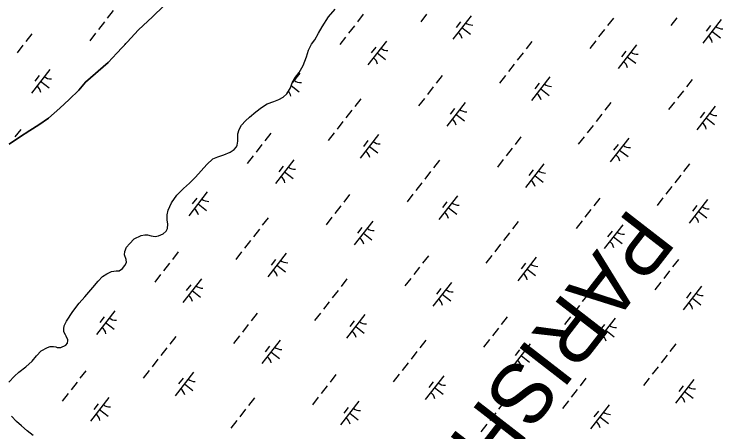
# Model space of a CAD drawing. Extents: x 3888273 to 3909528, y 158682 to 181032.
# Drawn here: x 3904884 to 3906064, y 170681 to 171377 of the extents above; entities that cross this region are included whole.
import ezdxf

# ---------------------------------------------------------------- set-up
doc = ezdxf.new("R2010")
doc.units = 0
for name, color, linetype in [('V-TOPO-GNAM-IDEN', 7, 'Continuous'), ('V-TOPO-SHOR', 7, 'Continuous'), ('V-WETL-SWMP', 7, 'Continuous')]:
    doc.layers.add(name, color=color, linetype=linetype)

msp = doc.modelspace()

# ---------------------------------------------------------------- linework, layer by layer
at = {"layer": 'V-TOPO-SHOR'}
for points in [[(3904875.2, 171160.3), (3904892.1, 171172), (3904909.5, 171183.3), (3904924.5, 171192.6), (3904940.7, 171203.9), (3904959.6, 171220.8), (3904975.3, 171235.2), (3904991, 171250.5), (3905002.4, 171263.7), (3905040.2, 171296.7), (3905054.7, 171312), (3905071.6, 171330.8), (3905090.9, 171350.9), (3905113.7, 171372.6), (3905132.6, 171391.4)], [(3905001.4, 170906.2), (3905014.3, 170921.4), (3905023.7, 170932.2), (3905030.7, 170939.8), (3905037.8, 170944.6), (3905045.7, 170948.2), (3905053.2, 170949.1), (3905058.3, 170949.5), (3905063.8, 170953.2), (3905068.1, 170958), (3905070.9, 170963.1), (3905070, 170968.3), (3905067.2, 170976.2), (3905067.9, 170981.7), (3905070.6, 170988.9), (3905075.7, 170994.5), (3905083.5, 171002.5), (3905094.9, 171008.1), (3905101.3, 171009.4), (3905105.6, 171009.4), (3905112, 171007.9), (3905118.3, 171006.4), (3905124.2, 171007.6), (3905131.7, 171011.3), (3905136.8, 171015.3), (3905138.8, 171020.1), (3905139.5, 171027.2), (3905138.6, 171034.3), (3905138.5, 171042.6), (3905140, 171050.6), (3905145.8, 171062.5), (3905154.4, 171075.3), (3905165.4, 171086.8), (3905175.6, 171095.7), (3905185.8, 171105.3), (3905195.2, 171116.1), (3905204.5, 171126.8), (3905214.7, 171136.1), (3905223, 171139.3), (3905232.9, 171142.6), (3905243.1, 171147), (3905249.8, 171151.9), (3905253.7, 171155.9), (3905254.9, 171158.7), (3905256.4, 171165.8), (3905255.9, 171177.7), (3905258.6, 171185.2), (3905262, 171192.4), (3905268.7, 171199.6), (3905275.4, 171205.6), (3905286, 171214.4), (3905295.8, 171221.6), (3905304.8, 171227.7), (3905315.9, 171231.7), (3905324.5, 171235), (3905331.6, 171239), (3905337.9, 171244.6), (3905343.7, 171254.6), (3905346.8, 171262.5), (3905352.3, 171272.1), (3905358.1, 171280.1), (3905365.1, 171291.6), (3905370.5, 171305.9), (3905373.6, 171317.1), (3905378.6, 171327), (3905384.5, 171334.6), (3905390.3, 171345.3), (3905396.5, 171356.1), (3905407.4, 171372.8), (3905418.4, 171385.6)], [(3904874.6, 170763.5), (3904884, 170773.9), (3904891.1, 170780.3), (3904902.9, 170789.2), (3904913.4, 170798.8), (3904920.9, 170807.6), (3904928.3, 170816), (3904939.3, 170821.6), (3904943.3, 170823.2), (3904948.8, 170823.3), (3904952.8, 170822.5), (3904955.2, 170821.8), (3904961.5, 170821.8), (3904969.4, 170825.5), (3904972.1, 170828.7), (3904972.9, 170833.4), (3904972.8, 170834.2), (3904970.4, 170840.5), (3904969.2, 170842.5), (3904966, 170847.6), (3904966.3, 170852.4), (3904966.7, 170857.5), (3904970.5, 170865.5), (3904981.5, 170881.8), (3904991.6, 170895.4), (3905001.4, 170906.2)], [(3904915.1, 170674.9), (3904905.2, 170682.7), (3904895.6, 170690.9), (3904887.6, 170698.3), (3904879.2, 170707)]]:
    msp.add_lwpolyline(points, dxfattribs=at)
at = {"layer": 'V-WETL-SWMP'}
for p, q in [((3905132.6, 171391.4), (3905113.7, 171372.6)), ((3905048.6, 171383.2), (3905038.7, 171370.6)), ((3905407.4, 171372.8), (3905418.4, 171385.6)), ((3905465.2, 171377), (3905455.4, 171364.3)), ((3905570.7, 171377.2), (3905560.9, 171364.6)), ((3905113.7, 171372.6), (3905090.9, 171350.9)), ((3905396.5, 171356.1), (3905407.4, 171372.8)), ((3905644.8, 171374.7), (3905614.1, 171335.3)), ((3905881.9, 171370.7), (3905872.1, 171358.1)), ((3905987.4, 171371), (3905977.5, 171358.4)), ((3906061.5, 171368.5), (3906030.8, 171329.1)), ((3905033.8, 171364.3), (3905024, 171351.6)), ((3905390.3, 171345.3), (3905396.5, 171356.1)), ((3905450.5, 171358), (3905440.7, 171345.4)), ((3905627.1, 171364.5), (3905619.7, 171355)), ((3905629.5, 171355), (3905643.7, 171344)), ((3906043.7, 171358.3), (3906036.4, 171348.8)), ((3904912.8, 171344.3), (3904903, 171331.7)), ((3905019.1, 171345.3), (3905009.3, 171332.7)), ((3905090.9, 171350.9), (3905071.6, 171330.8)), ((3905384.5, 171334.6), (3905390.3, 171345.3)), ((3905867.2, 171351.8), (3905857.3, 171339.2)), ((3906046.1, 171348.8), (3906060.4, 171337.7)), ((3905071.6, 171330.8), (3905054.7, 171312)), ((3905378.6, 171327), (3905384.5, 171334.6)), ((3905435.8, 171339.1), (3905425.9, 171326.5)), ((3905503.6, 171332.3), (3905472.9, 171292.8)), ((3905746.2, 171331.9), (3905736.4, 171319.3)), ((3905852.4, 171332.9), (3905842.6, 171320.2)), ((3904898.1, 171325.4), (3904888.3, 171312.8)), ((3905069.2, 171328.3), (3905068, 171326.7)), ((3905373.6, 171317.1), (3905378.6, 171327)), ((3905485.8, 171322), (3905478.5, 171312.6)), ((3905920.3, 171326.1), (3905889.6, 171286.6)), ((3905054.7, 171312), (3905040.2, 171296.7)), ((3905365.1, 171291.6), (3905370.5, 171305.9)), ((3905370.5, 171305.9), (3905373.6, 171317.1)), ((3905488.2, 171312.6), (3905502.4, 171301.5)), ((3905731.4, 171313), (3905721.6, 171300.3)), ((3905902.5, 171315.8), (3905895.1, 171306.3)), ((3905904.9, 171306.3), (3905919.1, 171295.3)), ((3905040.2, 171296.7), (3905002.4, 171263.7)), ((3905716.7, 171294), (3905706.9, 171281.4)), ((3904942.8, 171285), (3904912.1, 171245.6)), ((3905358.1, 171280.1), (3905365.1, 171291.6)), ((3904925, 171274.8), (3904917.7, 171265.3)), ((3905346.8, 171262.5), (3905352.3, 171272.1)), ((3905359.4, 171278.8), (3905346.9, 171262.7)), ((3905352.3, 171272.1), (3905358.1, 171280.1)), ((3905596.5, 171274.8), (3905586.7, 171262.2)), ((3905702, 171275.1), (3905692.1, 171262.4)), ((3905776.1, 171272.6), (3905745.4, 171233.1)), ((3904927.4, 171265.3), (3904941.6, 171254.3)), ((3905002.4, 171263.7), (3904991, 171250.5)), ((3905343.7, 171254.6), (3905346.8, 171262.5)), ((3905345.2, 171258.3), (3905358.3, 171248)), ((3905758.4, 171262.3), (3905751, 171252.9)), ((3906013.2, 171268.6), (3906003.4, 171256)), ((3904991, 171250.5), (3904975.3, 171235.2)), ((3905337.9, 171244.6), (3905343.7, 171254.6)), ((3905581.8, 171255.9), (3905571.9, 171243.3)), ((3905760.8, 171252.9), (3905775, 171241.8)), ((3905998.4, 171249.7), (3905988.6, 171237)), ((3904975.3, 171235.2), (3904959.6, 171220.8)), ((3905315.9, 171231.7), (3905324.5, 171235)), ((3905324.5, 171235), (3905331.6, 171239)), ((3905331.6, 171239), (3905337.9, 171244.6)), ((3905460.8, 171236), (3905451, 171223.3)), ((3905567, 171236.9), (3905557.2, 171224.3)), ((3905295.8, 171221.6), (3905304.8, 171227.7)), ((3905304.8, 171227.7), (3905315.9, 171231.7)), ((3905634.9, 171230.1), (3905604.2, 171190.7)), ((3905877.5, 171229.8), (3905867.6, 171217.1)), ((3905983.7, 171230.7), (3905973.9, 171218.1)), ((3906051.5, 171223.9), (3906020.8, 171184.5)), ((3904959.6, 171220.8), (3904940.7, 171203.9)), ((3905275.4, 171205.6), (3905286, 171214.4)), ((3905286, 171214.4), (3905295.8, 171221.6)), ((3905446.1, 171217), (3905436.2, 171204.4)), ((3905617.1, 171219.9), (3905609.7, 171210.4)), ((3906033.8, 171213.7), (3906026.4, 171204.2)), ((3904940.7, 171203.9), (3904924.5, 171192.6)), ((3905262, 171192.4), (3905268.7, 171199.6)), ((3905268.7, 171199.6), (3905275.4, 171205.6)), ((3905619.5, 171210.4), (3905633.7, 171199.4)), ((3905862.7, 171210.8), (3905852.9, 171198.2)), ((3906036.2, 171204.2), (3906050.4, 171193.1)), ((3904924.5, 171192.6), (3904909.5, 171183.3)), ((3905258.6, 171185.2), (3905262, 171192.4)), ((3905431.3, 171198.1), (3905421.5, 171185.5)), ((3905848, 171191.9), (3905838.2, 171179.2)), ((3904894.5, 171185.1), (3904884.6, 171172.5)), ((3904909.5, 171183.3), (3904892.1, 171172)), ((3905255.9, 171177.7), (3905258.6, 171185.2)), ((3905256.4, 171165.8), (3905255.9, 171177.7)), ((3905311.1, 171178.9), (3905301.3, 171166.3)), ((3905416.6, 171179.2), (3905406.8, 171166.5)), ((3905490.7, 171176.7), (3905460, 171137.2)), ((3904892.1, 171172), (3904875.2, 171160.3)), ((3905254.9, 171158.7), (3905256.4, 171165.8)), ((3905473, 171166.4), (3905465.6, 171156.9)), ((3905727.8, 171172.7), (3905718, 171160.1)), ((3905833.3, 171172.9), (3905823.4, 171160.3)), ((3905907.4, 171170.5), (3905876.7, 171131)), ((3905249.8, 171151.9), (3905253.7, 171155.9)), ((3905253.7, 171155.9), (3905254.9, 171158.7)), ((3905296.4, 171160), (3905286.6, 171147.3)), ((3905475.4, 171156.9), (3905489.6, 171145.9)), ((3905713.1, 171153.7), (3905703.2, 171141.1)), ((3905889.6, 171160.2), (3905882.3, 171150.7)), ((3905223, 171139.3), (3905232.9, 171142.6)), ((3905232.9, 171142.6), (3905243.1, 171147)), ((3905243.1, 171147), (3905249.8, 171151.9)), ((3905281.6, 171141), (3905271.8, 171128.4)), ((3905892, 171150.7), (3905906.2, 171139.7)), ((3905204.5, 171126.8), (3905214.7, 171136.1)), ((3905214.7, 171136.1), (3905223, 171139.3)), ((3905349.5, 171134.2), (3905318.8, 171094.8)), ((3905592.1, 171133.8), (3905582.3, 171121.2)), ((3905698.3, 171134.8), (3905688.5, 171122.2)), ((3905195.2, 171116.1), (3905204.5, 171126.8)), ((3905331.7, 171124), (3905324.4, 171114.5)), ((3905766.2, 171128), (3905735.4, 171088.5)), ((3905748.4, 171117.7), (3905741, 171108.3)), ((3906008.7, 171127.6), (3905998.9, 171115)), ((3905175.6, 171095.7), (3905185.8, 171105.3)), ((3905185.8, 171105.3), (3905195.2, 171116.1)), ((3905334.1, 171114.5), (3905348.3, 171103.4)), ((3905577.3, 171114.9), (3905567.5, 171102.3)), ((3905750.8, 171108.3), (3905765, 171097.2)), ((3905994, 171108.7), (3905984.2, 171096)), ((3905165.4, 171086.8), (3905175.6, 171095.7)), ((3905562.6, 171095.9), (3905552.8, 171083.3)), ((3905154.4, 171075.3), (3905165.4, 171086.8)), ((3905979.3, 171089.7), (3905969.4, 171077.1)), ((3905145.8, 171062.5), (3905154.4, 171075.3)), ((3905205.3, 171080.8), (3905174.6, 171041.3)), ((3905187.6, 171070.5), (3905180.2, 171061)), ((3905442.4, 171076.8), (3905432.6, 171064.1)), ((3905547.9, 171077), (3905538, 171064.4)), ((3905622, 171074.5), (3905591.3, 171035.1)), ((3905859.1, 171070.5), (3905849.2, 171057.9)), ((3905964.5, 171070.8), (3905954.7, 171058.2)), ((3905140, 171050.6), (3905145.8, 171062.5)), ((3905190, 171061), (3905204.2, 171050)), ((3905427.7, 171057.8), (3905417.8, 171045.2)), ((3905604.3, 171064.3), (3905596.9, 171054.8)), ((3906038.7, 171068.3), (3906008, 171028.8)), ((3906020.9, 171058), (3906013.5, 171048.6)), ((3905138.5, 171042.6), (3905140, 171050.6)), ((3905606.7, 171054.8), (3905620.9, 171043.7)), ((3905844.3, 171051.6), (3905834.5, 171039)), ((3906023.3, 171048.6), (3906037.5, 171037.5)), ((3905138.6, 171034.3), (3905138.5, 171042.6)), ((3905139.5, 171027.2), (3905138.6, 171034.3)), ((3905306.7, 171037.9), (3905296.9, 171025.3)), ((3905412.9, 171038.9), (3905403.1, 171026.3)), ((3905138.8, 171020.1), (3905139.5, 171027.2)), ((3905480.8, 171032.1), (3905450.1, 170992.6)), ((3905723.4, 171031.7), (3905713.5, 171019.1)), ((3905829.6, 171032.7), (3905819.8, 171020)), ((3905897.4, 171025.9), (3905866.7, 170986.4)), ((3905124.2, 171007.6), (3905131.7, 171011.3)), ((3905131.7, 171011.3), (3905136.8, 171015.3)), ((3905136.8, 171015.3), (3905138.8, 171020.1)), ((3905292, 171019), (3905282.1, 171006.3)), ((3905463, 171021.8), (3905455.6, 171012.4)), ((3905465.4, 171012.4), (3905479.6, 171001.3)), ((3905708.6, 171012.7), (3905698.8, 171000.1)), ((3905879.7, 171015.6), (3905872.3, 171006.1)), ((3905075.7, 170994.5), (3905083.5, 171002.5)), ((3905083.5, 171002.5), (3905094.9, 171008.1)), ((3905094.9, 171008.1), (3905101.3, 171009.4)), ((3905101.3, 171009.4), (3905105.6, 171009.4)), ((3905105.6, 171009.4), (3905112, 171007.9)), ((3905112, 171007.9), (3905118.3, 171006.4)), ((3905118.3, 171006.4), (3905124.2, 171007.6)), ((3905277.2, 171000), (3905267.4, 170987.4)), ((3905882.1, 171006.1), (3905896.3, 170995.1)), ((3905067.9, 170981.7), (3905070.6, 170988.9)), ((3905070.6, 170988.9), (3905075.7, 170994.5)), ((3905693.9, 170993.8), (3905684.1, 170981.2)), ((3905067.2, 170976.2), (3905067.9, 170981.7)), ((3905070, 170968.3), (3905067.2, 170976.2)), ((3905157, 170980.8), (3905147.2, 170968.2)), ((3905262.5, 170981.1), (3905252.7, 170968.5)), ((3905336.6, 170978.6), (3905305.9, 170939.2)), ((3905068.1, 170958), (3905070.9, 170963.1)), ((3905070.9, 170963.1), (3905070, 170968.3)), ((3905318.9, 170968.4), (3905311.5, 170958.9)), ((3905573.7, 170974.6), (3905563.9, 170962)), ((3905679.1, 170974.9), (3905669.3, 170962.2)), ((3905753.3, 170972.4), (3905722.6, 170932.9)), ((3905990.3, 170968.4), (3905980.5, 170955.8)), ((3905058.3, 170949.5), (3905063.8, 170953.2)), ((3905063.8, 170953.2), (3905068.1, 170958)), ((3905142.3, 170961.9), (3905132.5, 170949.3)), ((3905321.3, 170958.9), (3905335.5, 170947.8)), ((3905558.9, 170955.7), (3905549.1, 170943)), ((3905735.5, 170962.1), (3905728.2, 170952.7)), ((3905737.9, 170952.7), (3905752.1, 170941.6)), ((3905023.7, 170932.2), (3905030.7, 170939.8)), ((3905030.7, 170939.8), (3905037.8, 170944.6)), ((3905037.8, 170944.6), (3905045.7, 170948.2)), ((3905045.7, 170948.2), (3905053.2, 170949.1)), ((3905053.2, 170949.1), (3905058.3, 170949.5)), ((3905127.5, 170943), (3905117.7, 170930.3)), ((3905975.6, 170949.5), (3905965.8, 170936.8)), ((3905014.3, 170921.4), (3905023.7, 170932.2)), ((3905195.4, 170936.2), (3905164.7, 170896.7)), ((3905438, 170935.8), (3905428.1, 170923.1)), ((3905544.2, 170936.7), (3905534.4, 170924.1)), ((3905612, 170929.9), (3905581.3, 170890.5)), ((3905854.6, 170929.5), (3905844.8, 170916.9)), ((3905960.9, 170930.5), (3905951, 170917.9)), ((3905001.4, 170906.2), (3905014.3, 170921.4)), ((3905177.6, 170925.9), (3905170.3, 170916.4)), ((3905180, 170916.4), (3905194.2, 170905.4)), ((3905423.2, 170916.8), (3905413.4, 170904.2)), ((3905594.3, 170919.7), (3905586.9, 170910.2)), ((3906028.7, 170923.7), (3905998, 170884.3)), ((3904991.6, 170895.4), (3905001.4, 170906.2)), ((3905596.7, 170910.2), (3905610.9, 170899.2)), ((3905839.9, 170910.6), (3905830.1, 170898)), ((3906011, 170913.5), (3906003.6, 170904)), ((3904981.5, 170881.8), (3904991.6, 170895.4)), ((3905408.5, 170897.9), (3905398.7, 170885.3)), ((3906013.4, 170904), (3906027.6, 170892.9)), ((3904970.5, 170865.5), (3904981.5, 170881.8)), ((3905051.2, 170882.7), (3905020.5, 170843.2)), ((3905825.2, 170891.7), (3905815.3, 170879)), ((3905033.5, 170872.4), (3905026.1, 170863)), ((3905288.3, 170878.7), (3905278.5, 170866.1)), ((3905393.8, 170878.9), (3905383.9, 170866.3)), ((3905467.9, 170876.5), (3905437.2, 170837)), ((3905705, 170872.5), (3905695.1, 170859.8)), ((3905810.4, 170872.7), (3905800.6, 170860.1)), ((3905884.6, 170870.2), (3905853.9, 170830.8)), ((3904966.3, 170852.4), (3904966.7, 170857.5)), ((3904966.7, 170857.5), (3904970.5, 170865.5)), ((3905035.9, 170863), (3905050.1, 170851.9)), ((3905273.6, 170859.8), (3905263.7, 170847.1)), ((3905450.1, 170866.2), (3905442.8, 170856.7)), ((3905866.8, 170860), (3905859.4, 170850.5)), ((3904966, 170847.6), (3904966.3, 170852.4)), ((3904969.2, 170842.5), (3904966, 170847.6)), ((3905452.5, 170856.7), (3905466.8, 170845.7)), ((3905690.2, 170853.5), (3905680.4, 170840.9)), ((3905869.2, 170850.5), (3905883.4, 170839.5)), ((3904970.4, 170840.5), (3904969.2, 170842.5)), ((3904972.8, 170834.2), (3904970.4, 170840.5)), ((3904972.1, 170828.7), (3904972.9, 170833.4)), ((3904972.9, 170833.4), (3904972.8, 170834.2)), ((3905152.6, 170839.8), (3905142.8, 170827.2)), ((3905258.8, 170840.8), (3905249, 170828.2)), ((3905326.7, 170834), (3905296, 170794.6)), ((3905569.3, 170833.6), (3905559.4, 170821)), ((3905675.5, 170834.6), (3905665.7, 170822)), ((3904928.3, 170816), (3904939.3, 170821.6)), ((3904939.3, 170821.6), (3904943.3, 170823.2)), ((3904943.3, 170823.2), (3904948.8, 170823.3)), ((3904948.8, 170823.3), (3904952.8, 170822.5)), ((3904952.8, 170822.5), (3904955.2, 170821.8)), ((3904955.2, 170821.8), (3904961.5, 170821.8)), ((3904961.5, 170821.8), (3904969.4, 170825.5)), ((3904969.4, 170825.5), (3904972.1, 170828.7)), ((3905308.9, 170823.8), (3905301.5, 170814.3)), ((3905743.3, 170827.8), (3905712.6, 170788.3)), ((3905985.9, 170827.4), (3905976.1, 170814.8)), ((3904920.9, 170807.6), (3904928.3, 170816)), ((3905137.8, 170820.9), (3905128, 170808.3)), ((3905311.3, 170814.3), (3905325.5, 170803.2)), ((3905554.5, 170814.7), (3905544.7, 170802.1)), ((3905725.6, 170817.5), (3905718.2, 170808.1)), ((3904902.9, 170789.2), (3904913.4, 170798.8)), ((3904913.4, 170798.8), (3904920.9, 170807.6)), ((3905123.1, 170802), (3905113.3, 170789.3)), ((3905728, 170808.1), (3905742.2, 170797)), ((3905971.2, 170808.5), (3905961.4, 170795.8)), ((3904891.1, 170780.3), (3904902.9, 170789.2)), ((3905539.8, 170795.7), (3905530, 170783.1)), ((3905956.4, 170789.5), (3905946.6, 170776.9)), ((3904884, 170773.9), (3904891.1, 170780.3)), ((3905002.9, 170782.8), (3904993.1, 170770.2)), ((3905108.4, 170783), (3905098.5, 170770.4)), ((3905182.5, 170780.6), (3905151.8, 170741.1)), ((3905419.6, 170776.6), (3905409.8, 170763.9)), ((3905525, 170776.8), (3905515.2, 170764.2)), ((3905599.2, 170774.3), (3905568.5, 170734.9)), ((3904874.6, 170763.5), (3904884, 170773.9)), ((3904988.2, 170763.8), (3904978.3, 170751.2)), ((3905164.8, 170770.3), (3905157.4, 170760.8)), ((3905581.4, 170764.1), (3905574.1, 170754.6)), ((3905836.2, 170770.3), (3905826.4, 170757.7)), ((3905941.7, 170770.6), (3905931.9, 170757.9)), ((3906015.8, 170768.1), (3905985.1, 170728.6)), ((3905167.2, 170760.8), (3905181.4, 170749.8)), ((3905404.8, 170757.6), (3905395, 170745)), ((3905583.8, 170754.6), (3905598, 170743.5)), ((3905821.5, 170751.4), (3905811.7, 170738.8)), ((3905998.1, 170757.8), (3905990.7, 170748.4)), ((3904973.4, 170744.9), (3904963.6, 170732.3)), ((3906000.5, 170748.4), (3906014.7, 170737.3)), ((3905041.3, 170738.1), (3905010.6, 170698.6)), ((3905023.5, 170727.8), (3905016.1, 170718.4)), ((3905283.9, 170737.7), (3905274, 170725.1)), ((3905390.1, 170738.7), (3905380.3, 170726)), ((3905457.9, 170731.9), (3905427.2, 170692.4)), ((3905700.5, 170731.5), (3905690.7, 170718.9)), ((3905806.8, 170732.4), (3905796.9, 170719.8)), ((3905025.9, 170718.4), (3905040.1, 170707.3)), ((3905269.1, 170718.8), (3905259.3, 170706.1)), ((3905440.2, 170721.6), (3905432.8, 170712.1)), ((3905874.6, 170725.7), (3905843.9, 170686.2)), ((3905856.9, 170715.4), (3905849.5, 170705.9)), ((3904887.6, 170698.3), (3904879.2, 170707)), ((3905442.6, 170712.1), (3905456.8, 170701.1)), ((3905685.8, 170712.5), (3905676, 170699.9)), ((3905859.3, 170705.9), (3905873.5, 170694.9)), ((3904895.6, 170690.9), (3904887.6, 170698.3)), ((3905254.4, 170699.8), (3905244.6, 170687.2)), ((3905671.1, 170693.6), (3905661.2, 170681)), ((3904905.2, 170682.7), (3904895.6, 170690.9)), ((3904915.1, 170674.9), (3904905.2, 170682.7))]:
    msp.add_line(p, q, dxfattribs=at)
for centre, start, end in [((3905646.6, 171376.7), 231.343, 272.8866), ((3906063.3, 171370.4), 231.343, 272.8866), ((3905612.7, 171333.1), 11.343, 52.8866), ((3906029.4, 171326.8), 11.343, 52.8866), ((3905505.4, 171334.2), 231.343, 272.8866), ((3905922.1, 171328), 231.343, 272.8866), ((3905471.5, 171290.6), 11.343, 52.8866), ((3905888.1, 171284.4), 11.343, 52.8866), ((3904944.6, 171287), 231.343, 272.8866), ((3905361.2, 171280.7), 231.343, 272.8866), ((3905777.9, 171274.5), 231.343, 272.8866), ((3904910.7, 171243.4), 11.343, 52.8866), ((3905327.3, 171237.1), 11.343, 41.9789), ((3905744, 171230.9), 11.343, 52.8866), ((3905636.7, 171232.1), 231.343, 272.8866), ((3906053.3, 171225.8), 231.343, 272.8866), ((3905602.7, 171188.5), 11.343, 52.8866), ((3906019.4, 171182.2), 11.343, 52.8866), ((3905492.5, 171178.6), 231.343, 272.8866), ((3905909.2, 171172.4), 231.343, 272.8866), ((3905458.6, 171135), 11.343, 52.8866), ((3905875.3, 171128.8), 11.343, 52.8866), ((3905351.3, 171136.2), 231.343, 272.8866), ((3905317.4, 171092.6), 11.343, 52.8866), ((3905768, 171129.9), 231.343, 272.8866), ((3905734, 171086.3), 11.343, 52.8866), ((3905207.1, 171082.7), 231.343, 272.8866), ((3905623.8, 171076.5), 231.343, 272.8866), ((3905173.2, 171039.1), 11.343, 52.8866), ((3905589.9, 171032.9), 11.343, 52.8866), ((3906040.5, 171070.2), 231.343, 272.8866), ((3906006.5, 171026.6), 11.343, 52.8866), ((3905482.6, 171034), 231.343, 272.8866), ((3905899.2, 171027.8), 231.343, 272.8866), ((3905448.6, 170990.4), 11.343, 52.8866), ((3905865.3, 170984.2), 11.343, 52.8866), ((3905338.4, 170980.5), 231.343, 272.8866), ((3905755.1, 170974.3), 231.343, 272.8866), ((3905304.5, 170936.9), 11.343, 52.8866), ((3905721.2, 170930.7), 11.343, 52.8866), ((3905197.2, 170938.1), 231.343, 272.8866), ((3905613.8, 170931.9), 231.343, 272.8866), ((3905163.3, 170894.5), 11.343, 52.8866), ((3906030.5, 170925.6), 231.343, 272.8866), ((3905579.9, 170888.3), 11.343, 52.8866), ((3905996.6, 170882), 11.343, 52.8866), ((3905053, 170884.6), 231.343, 272.8866), ((3905469.7, 170878.4), 231.343, 272.8866), ((3905886.4, 170872.2), 231.343, 272.8866), ((3905019.1, 170841), 11.343, 52.8866), ((3905435.8, 170834.8), 11.343, 52.8866), ((3905852.4, 170828.6), 11.343, 52.8866), ((3905328.5, 170835.9), 231.343, 272.8866), ((3905745.1, 170829.7), 231.343, 272.8866), ((3905294.5, 170792.3), 11.343, 52.8866), ((3905711.2, 170786.1), 11.343, 52.8866), ((3905184.3, 170782.5), 231.343, 272.8866), ((3905601, 170776.2), 231.343, 272.8866), ((3905150.4, 170738.9), 11.343, 52.8866), ((3906017.6, 170770), 231.343, 272.8866), ((3905567.1, 170732.6), 11.343, 52.8866), ((3905983.7, 170726.4), 11.343, 52.8866), ((3905043.1, 170740), 231.343, 272.8866), ((3905459.7, 170733.8), 231.343, 272.8866), ((3905009.1, 170696.4), 11.343, 52.8866), ((3905425.8, 170690.2), 11.343, 52.8866), ((3905876.4, 170727.6), 231.343, 272.8866), ((3905842.5, 170684), 11.343, 52.8866)]:
    msp.add_arc(centre, 17.6, start, end, dxfattribs=at)

# ---------------------------------------------------------------- texts
at = {"layer": 'V-TOPO-GNAM-IDEN'}
msp.add_text('PARISH,', height=100, rotation=232.2195, dxfattribs=at).set_placement((3905909.4, 171057.6))

doc.saveas('drawing.dxf')
